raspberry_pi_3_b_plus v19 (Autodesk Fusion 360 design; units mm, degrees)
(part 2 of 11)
sketch "Sketch5" plane through (-0.5, 0, 0) normal (1, 0, 0) x axis (0, 0, -1)
  line L1 (-2.15, -3.125) -> (-2.15, -2.75)
  line L2 (-0.6, -3.425) -> (-1.85, -3.425)
  line L3 (-0.3, -1.71) -> (-0.3, -3.125)
  line L4 (0, -1.71) -> (-0.3, -1.71)
  line L5 (0, 1.71) -> (0, -1.71)
  line L6 (-0.3, 1.71) -> (0, 1.71)
  line L7 (-0.3, 3.125) -> (-0.3, 1.71)
  line L8 (-1.85, 3.425) -> (-0.6, 3.425)
  line L9 (-2.15, 2.75) -> (-2.15, 3.125)
  line L10 (-1.8, 2.4) -> (-2.15, 2.75)
  line L11 (-1.8, 1.9) -> (-1.8, 2.4)
  line L12 (-2.15, 1.55) -> (-1.8, 1.9)
  line L13 (-2.15, -1.55) -> (-2.15, 1.55)
  line L14 (-1.8, -1.9) -> (-2.15, -1.55)
  line L15 (-1.8, -2.4) -> (-1.8, -1.9)
  line L16 (-2.15, -2.75) -> (-1.8, -2.4)
  line L17 (-1.82, 1.74) -> (-1.82, -1.74)
  line L18 (-1.22, 1.74) -> (-1.82, 1.74)
  line L19 (-1.22, 1.5) -> (-1.22, 1.74)
  line L20 (-1.37, 1.5) -> (-1.22, 1.5)
  line L21 (-1.37, 1.1) -> (-1.37, 1.5)
  line L22 (-1.22, 1.1) -> (-1.37, 1.1)
  line L23 (-1.22, 0.85) -> (-1.22, 1.1)
  line L24 (-1.37, 0.85) -> (-1.22, 0.85)
  line L25 (-1.37, 0.45) -> (-1.37, 0.85)
  line L26 (-1.22, 0.45) -> (-1.37, 0.45)
  line L27 (-1.22, 0.2) -> (-1.22, 0.45)
  line L28 (-1.37, 0.2) -> (-1.22, 0.2)
  line L29 (-1.37, -0.2) -> (-1.37, 0.2)
  line L30 (-1.22, -0.2) -> (-1.37, -0.2)
  line L31 (-1.22, -0.45) -> (-1.22, -0.2)
  line L32 (-1.37, -0.45) -> (-1.22, -0.45)
  line L33 (-1.37, -0.85) -> (-1.37, -0.45)
  line L34 (-1.22, -0.85) -> (-1.37, -0.85)
  line L35 (-1.22, -1.1) -> (-1.22, -0.85)
  line L36 (-1.37, -1.1) -> (-1.22, -1.1)
  line L37 (-1.37, -1.5) -> (-1.37, -1.1)
  line L38 (-1.22, -1.5) -> (-1.37, -1.5)
  line L39 (-1.22, -1.74) -> (-1.22, -1.5)
  line L40 (-1.82, -1.74) -> (-1.22, -1.74)
  line L41 (-1.82, 0) -> (0, 0)
  arc A1 centre (-1.85, -3.125) radius 0.3 clockwise from (-1.85, -3.425) to (-2.15, -3.125)
  arc A2 centre (-0.6, -3.125) radius 0.3 clockwise from (-0.3, -3.125) to (-0.6, -3.425)
  arc A3 centre (-0.6, 3.125) radius 0.3 clockwise from (-0.6, 3.425) to (-0.3, 3.125)
  arc A4 centre (-1.85, 3.125) radius 0.3 clockwise from (-2.15, 3.125) to (-1.85, 3.425)
  point P1 (0, 0)
  point P50 (0, 0)
  point P51 (-1.82, 0)
  point P27 (-1.82, 1.74)
  point P28 (-1.22, 1.74)
  vertical L29
  vertical L17
  horizontal L18
  horizontal L20
  vertical L21
  horizontal L22
  vertical L23
  horizontal L24
  vertical L25
  horizontal L26
  vertical L27
  horizontal L28
  horizontal L30
  vertical L31
  horizontal L32
  horizontal L34
  vertical L35
  horizontal L36
  vertical L33
  vertical L37
  horizontal L38
  vertical L39
  horizontal L40
  vertical L19
  collinear L27 L31
  collinear L23 L31
  collinear L19 L31
  collinear L31 L35
  collinear L31 L39
  collinear L29 L33
  collinear L29 L37
  collinear L25 L29
  collinear L21 L29
  equal L21 L29
  equal L25 L29
  equal L29 L33
  equal L29 L37
  equal L31 L35
  equal L27 L31
  equal L23 L31
  equal L19 L39
  coincident P1 P50
  midpoint L17 P51
  horizontal L41
  dimension "d174" distance L13 L17 = 0.33
  dimension "d175" distance L18 L40 = 3.48
  dimension "d178" distance L30 L32 = 0.25
  dimension "d179" distance L28 L30 = 0.4
  dimension "d180" distance P27 P28 = 0.6
  dimension "d181" distance L19 L21 = 0.15
extrude "Extrude6" add sketch "Sketch5" profile of L17 L18 L19 L20 L21 L22 L23 L24 L25 L26 L27 L28 L29 L30 L31 L32 L33 L34 L35 L36 L37 L38 L39 L40 along normal blind 2.68
fillet "Fillet2" radius 0.2
fillet "Fillet3" radius 0.1
fillet "Fillet4" radius 0.05
sketch "Sketch1" plane through (0, 0, 1.82) normal (0, 0, 1) x axis (1, 0, 0)
  line L1 (-0.5, -1.54) -> (-0.5, 1.54)
  line L2 (1.4, 1.45) -> (1.06, 1.45)
  line L3 (1.03, 0.45) -> (1.43, 0.45)
  line L4 (1.03, 1.42) -> (1.03, 0.45)
  line L5 (1.98, 1.54) -> (1.98, -1.54)
  line L6 (1.03, 0.2) -> (1.03, -0.2)
  line L7 (1.43, -0.2) -> (1.43, 0.2)
  line L8 (1.03, -0.2) -> (1.43, -0.2)
  line L9 (1.43, 0.2) -> (1.03, 0.2)
  line L10 (1.43, 0.45) -> (1.43, 1.42)
  line L11 (-1.2, 2.7457) -> (-1.2, 3.4)
  line L12 (-0.9634, 1.4482) -> (-1.0866, 1.6618)
  line L13 (-0.8, 3.4) -> (-0.8, 1.6)
  line L14 (-0.65, 1.45) -> (-0.55, 1.45)
  line L15 (-0.5, 1.5) -> (-0.5, 1.54)
  line L16 (-0.5, 1.54) -> (1.98, 1.54)
  line L17 (-1.1146, 2.6396) -> (-1.1854, 2.7104)
  line L18 (-0.95, 0.3464) -> (-0.95, 1.3982)
  line L19 (-1.2, 3.4) -> (-0.8, 3.4)
  line L20 (-1.1, 1.7118) -> (-1.1, 2.6043)
  line L21 (1.98, 0) -> (-0.95, 0)
  line L22 (1.03, -0.2) -> (1.43, 0.2)
  line L23 (1.43, -0.2) -> (1.03, 0.2)
  line L24 (-0.5, -1.54) -> (1.98, -1.54)
  line L25 (-0.5, -1.5) -> (-0.5, -1.54)
  line L26 (-0.65, -1.45) -> (-0.55, -1.45)
  line L27 (-0.8, -3.4) -> (-0.8, -1.6)
  line L28 (-1.2, -3.4) -> (-0.8, -3.4)
  line L29 (-1.2, -2.7457) -> (-1.2, -3.4)
  line L30 (-1.1146, -2.6396) -> (-1.1854, -2.7104)
  line L31 (-1.1, -1.7118) -> (-1.1, -2.6043)
  line L32 (-0.9634, -1.4482) -> (-1.0866, -1.6618)
  line L33 (-0.95, -0.3464) -> (-0.95, -1.3982)
  line L34 (1.4, -1.45) -> (1.06, -1.45)
  line L35 (1.43, -0.45) -> (1.43, -1.42)
  line L36 (1.03, -0.45) -> (1.43, -0.45)
  line L37 (1.03, -1.42) -> (1.03, -0.45)
  line L38 (-0.95, 1.425) -> (-0.95, 1.3982)
  line L39 (-0.95, 1.425) -> (-0.9634, 1.4482)
  line L40 (-1.1, 2.625) -> (-1.1, 2.6043)
  line L41 (-1.1, 2.625) -> (-1.1146, 2.6396)
  line L42 (1.98, -1.54) -> (-0.5, -1.54)
  line L43 (1.98, 1.54) -> (1.98, -1.54)
  line L44 (-0.5, 1.54) -> (1.98, 1.54)
  arc A1 centre (-0.65, 1.6) radius 0.15 clockwise from (-0.65, 1.45) to (-0.8, 1.6)
  arc A2 centre (-0.9, 0.3464) radius 0.05 clockwise from (-0.9071, 0.2969) to (-0.95, 0.3464)
  arc A3 centre (-1.05, 1.3982) radius 0.1 clockwise from (-0.9634, 1.4482) to (-0.95, 1.3982)
  circle C1 centre (-0.5, 0.75) radius 0.3
  arc A4 centre (1.06, 1.42) radius 0.03 clockwise from (1.03, 1.42) to (1.06, 1.45)
  arc A5 centre (-0.55, 1.5) radius 0.05 clockwise from (-0.5, 1.5) to (-0.55, 1.45)
  arc A6 centre (-1, 1.7118) radius 0.1 clockwise from (-1.0866, 1.6618) to (-1.1, 1.7118)
  arc A7 centre (1.4, 1.42) radius 0.03 clockwise from (1.4, 1.45) to (1.43, 1.42)
  arc A8 centre (-0.95, 0) radius 0.3 clockwise from (-0.9071, 0.2969) to (-0.9071, -0.2969)
  arc A9 centre (-1.15, 2.7457) radius 0.05 clockwise from (-1.1854, 2.7104) to (-1.2, 2.7457)
  arc A10 centre (-1.15, 2.6043) radius 0.05 clockwise from (-1.1146, 2.6396) to (-1.1, 2.6043)
  arc A11 centre (-0.55, -1.5) radius 0.05 clockwise from (-0.55, -1.45) to (-0.5, -1.5)
  arc A12 centre (-0.65, -1.6) radius 0.15 clockwise from (-0.8, -1.6) to (-0.65, -1.45)
  arc A13 centre (-1.15, -2.7457) radius 0.05 clockwise from (-1.2, -2.7457) to (-1.1854, -2.7104)
  arc A14 centre (-1.15, -2.6043) radius 0.05 clockwise from (-1.1, -2.6043) to (-1.1146, -2.6396)
  arc A15 centre (-1, -1.7118) radius 0.1 clockwise from (-1.1, -1.7118) to (-1.0866, -1.6618)
  arc A16 centre (-1.05, -1.3982) radius 0.1 clockwise from (-0.95, -1.3982) to (-0.9634, -1.4482)
  arc A17 centre (-0.9, -0.3464) radius 0.05 clockwise from (-0.95, -0.3464) to (-0.9071, -0.2969)
  circle C2 centre (-0.5, -0.75) radius 0.3
  arc A18 centre (1.06, -1.42) radius 0.03 clockwise from (1.06, -1.45) to (1.03, -1.42)
  arc A19 centre (1.4, -1.42) radius 0.03 clockwise from (1.43, -1.42) to (1.4, -1.45)
  point P25 (-0.95, 0)
  point P47 (-0.95, 0)
  point P48 (1.98, 0)
  point P23 (-0.5, 0)
  point P32 (-0.95, 0.3464)
  point P49 (1.23, 0)
  point P50 (-1.1962, 2.7266)
  point P18 (-0.8, 3.4)
  point P59 (-0.8, -3.4)
  point P19 (-1.2, 3.4)
  point P60 (-1.2, -3.4)
  point P20 (-1.1146, 2.6396)
  point P64 (-1.1146, -2.6396)
  point P21 (-1.1, 1.7118)
  point P67 (-1.1, -1.7118)
  point P24 (-1.1854, 2.7104)
  point P63 (-1.1854, -2.7104)
  point P26 (-1.0866, 1.6618)
  point P69 (-1.0866, -1.6618)
  point P27 (-0.65, 1.45)
  point P56 (-0.65, -1.45)
  point P28 (-0.5, 1.5)
  point P53 (-0.5, -1.5)
  point P31 (-0.95, 1.3982)
  point P72 (-0.95, -1.3982)
  point P73 (-0.95, -0.3464)
  point P34 (-0.9071, 0.2969)
  point P75 (-0.9071, -0.2969)
  point P37 (-0.55, 1.45)
  point P55 (-0.55, -1.45)
  point P38 (-1.1, 2.6043)
  point P66 (-1.1, -2.6043)
  point P40 (-1.2, 2.7457)
  point P61 (-1.2, -2.7457)
  point P41 (-0.9634, 1.4482)
  point P70 (-0.9634, -1.4482)
  point P43 (1.98, 1.54)
  point P51 (1.98, -1.54)
  point P44 (-0.5, 1.54)
  point P52 (-0.5, -1.54)
  point P45 (-0.8, 1.6)
  point P58 (-0.8, -1.6)
  point P33 (-0.9071, -0.2969)
  point P4 (1.43, 1.42)
  point P82 (1.43, -1.42)
  point P5 (1.4, 1.45)
  point P80 (1.4, -1.45)
  point P12 (1.03, 0.45)
  point P84 (1.03, -0.45)
  point P14 (1.06, 1.45)
  point P78 (1.06, -1.45)
  point P15 (1.03, 1.42)
  point P79 (1.03, -1.42)
  point P17 (1.43, 0.45)
  point P83 (1.43, -0.45)
  point P42 (1.98, 1.54)
  point P16 (1.98, -1.54)
  point P10 (-0.5, 0.75)
  point P85 (-0.95, 1.425)
  point P86 (-1.1, 2.625)
  coincident P25 P47
  midpoint L5 P48
  horizontal L21
  coincident P23 L21
  vertical L5
  horizontal L16
  vertical L13
  horizontal L19
  vertical L11
  vertical L20
  vertical L18
  vertical L4
  vertical L10
  horizontal L2
  horizontal L3
  horizontal L9
  vertical L6
  vertical L7
  horizontal L8
  horizontal L14
  vertical L15
  tangent L11 A9
  tangent L17 A9
  tangent L17 A10
  tangent L20 A10
  tangent L20 A6
  tangent L12 A6
  tangent L12 A3
  tangent L18 A3
  tangent A1 L13
  tangent A1 L14
  tangent L14 A5
  tangent L15 A5
  tangent L18 A2
  tangent A2 A8
  vertical P25 P32
  tangent L10 A7
  tangent L2 A7
  tangent L2 A4
  tangent L4 A4
  collinear L7 L10
  collinear L4 L6
  midpoint L22 P49
  coincident L21 P49
  equal A5 A10
  equal A9 A10
  equal A2 A9
  equal A3 A6
  midpoint A9 P50
  equal A4 A7
  midpoint L1 P23
  symmetric P18 L21 P59
  symmetric P19 L21 P60
  symmetric P20 L21 P64
  symmetric P21 L21 P67
  symmetric P24 L21 P63
  symmetric P26 L21 P69
  symmetric P27 L21 P56
  symmetric P28 L21 P53
  symmetric P31 L21 P72
  symmetric P32 L21 P73
  symmetric P34 L21 P75
  symmetric P37 L21 P55
  symmetric P38 L21 P66
  symmetric P40 L21 P61
  symmetric P41 L21 P70
  symmetric P43 L21 P51
  symmetric P44 L21 P52
  symmetric P45 L21 P58
  symmetric A1 L21 A12
  symmetric A2 L21 A17
  symmetric A3 L21 A16
  symmetric A5 L21 A11
  symmetric A6 L21 A15
  symmetric A9 L21 A13
  symmetric A10 L21 A14
  coincident P33 P75
  symmetric P4 L21 P82
  symmetric P5 L21 P80
  symmetric P12 L21 P84
  symmetric P14 L21 P78
  symmetric P15 L21 P79
  symmetric P17 L21 P83
  symmetric C1 L21 C2
  symmetric A4 L21 A18
  symmetric A7 L21 A19
  tangent A3 L38
  tangent A3 L39
  tangent A10 L40
  parallel L20 L40
  tangent A10 L41
  parallel L17 L41
  coincident P42 P43
  coincident P16 P51
  coincident L1 P10
  dimension "d192" radius A8 = 0.3
  dimension "d193" diameter C1 = 0.6
  dimension "d195" distance P23 P25 = 0.45
  dimension "d196" distance L11 L13 = 0.4
  dimension "d197" distance L13 L20 = 0.3
  dimension "d200" distance P25 L19 = 3.4
  dimension "d201" distance P10 L21 = 0.75
  dimension "d203" distance L6 L7 = 0.4
  dimension "d204" distance L8 L9 = 0.4
  dimension "d206" distance L5 P49 = 0.75
  dimension "d208" distance L2 L3 = 1
  dimension "d209" distance L3 L9 = 0.25
  dimension "d210" radius A3 = 0.1
  dimension "d212" radius A1 = 0.15
  dimension "d213" radius A5 = 0.05
  dimension "d214" distance L14 L16 = 0.09
  dimension "d215" distance L13 L15 = 0.3
  dimension "d218" distance P23 L13 = 0.3
  dimension "d223" radius A7 = 0.03
  dimension "d225" angle L12 L18 = 150.018
  dimension "d227" distance L21 P85 = 1.425
  dimension "d228" angle L17 L20 = 135
  dimension "d229" distance P85 P86 = 1.2
face "Face1" sketch "Sketch1"
face "EdgeFlange2" FlangeHeight 0.16 FlangeAngle 90 BendRadius 0.05 TwoBendReliefSize 0.4
combine "Combine1"
sketch "Sketch1" plane through (0, 0, 1.37) normal (0, 0, -1) x axis (-1, 0, 0)
  line L1 (1.2, 0.175) -> (-1.3, 0.175)
  line L2 (1.2, -0.175) -> (1.2, 0.175)
  line L3 (-1.3, -0.175) -> (1.2, -0.175)
  line L4 (-1.3, 0.175) -> (-1.3, -0.175)
  line L5 (1.2, 0) -> (0, 0)
  point P1 (0, 0)
  point P6 (0, 0)
  point P7 (1.2, 0)
  horizontal L1
  vertical L2
  horizontal L3
  vertical L4
  coincident P1 P6
  midpoint L2 P7
  horizontal L5
  dimension "d239" distance L2 L4 = 2.5
  dimension "d240" distance L1 L3 = 0.35
  dimension "d241" distance P1 L2 = 1.2
face "Face1" sketch "Sketch1"
face "EdgeFlange2" FlangeHeight 0.3 FlangeAngle 90
face "EdgeFlange3" FlangeHeight 1.5 FlangeAngle 90
face "EdgeFlange4" FlangeHeight 0.8 FlangeAngle 90
step "Unfold1"
sketch "Sketch2" plane through (0, 0, 1.37) normal (0, 0, 1) x axis (1, 0, 0)
  line L1 (-2.5467, 0.175) -> (-2.5467, -0.175)
  line L2 (-3.1867, 0.175) -> (-2.5467, 0.175)
  line L3 (-3.1867, -0.175) -> (-3.1867, 0.175)
  line L4 (-2.5467, -0.175) -> (-3.1867, -0.175)
  line L5 (-4.3006, 0) -> (0, 0)
  line L6 (-0.9766, 0.125) -> (-3.1867, 0.125)
  line L7 (-1.04, 0.175) -> (1.14, 0.175)
  line L8 (-1.2034, 0.175) -> (-1.04, 0.175)
  line L9 (-2.3834, 0.175) -> (-1.2034, 0.175)
  line L10 (-2.3834, 0.175) -> (-2.5467, 0.175)
  line L11 (-2.3834, -0.175) -> (-2.5467, -0.175)
  line L12 (-1.2034, -0.175) -> (-2.3834, -0.175)
  line L13 (-1.04, -0.175) -> (-1.2034, -0.175)
  line L14 (1.14, -0.175) -> (-1.04, -0.175)
  line L15 (-0.9766, -0.125) -> (-3.1867, -0.125)
  arc A1 centre (-0.9766, 0.175) radius 0.05 clockwise from (-0.9333, 0.15) to (-0.9766, 0.125)
  arc A2 centre (-0.89, 0.125) radius 0.05 clockwise from (-0.9333, 0.15) to (-0.89, 0.175)
  arc A3 centre (-0.9766, -0.175) radius 0.05 clockwise from (-0.9766, -0.125) to (-0.9333, -0.15)
  arc A4 centre (-0.89, -0.125) radius 0.05 clockwise from (-0.89, -0.175) to (-0.9333, -0.15)
  point P1 (0, 0)
  point P6 (0, 0)
  point P8 (-3.1867, 0.125)
  point P12 (-0.89, 0.175)
  point P24 (-3.1867, -0.125)
  point P9 (-0.9766, 0.125)
  point P25 (-0.9766, -0.125)
  point P10 (-0.9333, 0.15)
  point P27 (-0.9333, -0.15)
  point P29 (-0.89, -0.175)
  point P15 (-1.04, 0.175)
  coincident P1 P6
  horizontal L5
  coincident L3 P8
  tangent L6 A1
  tangent A1 A2
  horizontal L6
  coincident P12 L7
  tangent A2 L7
  symmetric L5 P8 P24
  symmetric L5 P9 P25
  symmetric L5 P10 P27
  symmetric L5 A1 A3
  symmetric L5 P12 P29
  symmetric L5 A2 A4
  equal A1 A2
  dimension "d248" distance L6 L15 = 0.25
  dimension "d250" radius A1 = 0.05
  dimension "d251" distance P12 P15 = 0.15
extrude "Extrude1" cut sketch "Sketch2" profile of L2 L3 L4 L6 A1 A2 L7 L8 L9 L10 L11 L12 L13 L14 L15 A3 A4 no distance stored
step "Refold1"
rectangular_pattern "㐁" uSpaceDistance 0.65 vSpaceDistance 0
combine "Combine2"
sketch "Sketch8" plane through (2.03, 0, 0) normal (-1, 0, 0) x axis (0, 0, 1)
  line L1 (2.15, 1.975) -> (2.45, 1.975)
  line L2 (2.45, 2.775) -> (2.15, 2.775)
  line L3 (2.45, 1.975) -> (2.45, 2.775)
  line L4 (2.15, 1.975) -> (2.15, 2.775)
  line L5 (2.6, 2.2348) -> (2.6, 2.5152)
  line L6 (2.45, 2.375) -> (2.6, 2.375)
  line L7 (2.32, 2.3023) -> (2.32, 2.4477)
  arc A1 centre (2.35, 2.5152) radius 0.25 clockwise from (2.475, 2.7317) to (2.6, 2.5152)
  arc A2 centre (2.5, 2.775) radius 0.05 clockwise from (2.475, 2.7317) to (2.45, 2.775)
  arc A3 centre (2.35, 2.2348) radius 0.25 clockwise from (2.6, 2.2348) to (2.475, 2.0183)
  arc A4 centre (2.5, 1.975) radius 0.05 clockwise from (2.45, 1.975) to (2.475, 2.0183)
  arc A5 centre (2.5, 2.775) radius 0.35 clockwise from (2.2988, 2.4886) to (2.15, 2.775)
  arc A6 centre (2.5, 1.975) radius 0.35 clockwise from (2.15, 1.975) to (2.2988, 2.2614)
  arc A7 centre (2.27, 2.4477) radius 0.05 clockwise from (2.2988, 2.4886) to (2.32, 2.4477)
  arc A8 centre (2.27, 2.3023) radius 0.05 clockwise from (2.32, 2.3023) to (2.2988, 2.2614)
  point P11 (2.6, 2.375)
  point P12 (2.45, 2.375)
  point P6 (2.45, 2.775)
  point P15 (2.45, 2.775)
  point P13 (2.475, 2.7317)
  point P19 (2.475, 2.0183)
  point P21 (2.45, 1.975)
  point P23 (2.2988, 2.4886)
  point P25 (2.2988, 2.2614)
  point P4 (2.15, 2.775)
  point P24 (2.15, 2.775)
  vertical L5
  midpoint L5 P11
  midpoint L3 P12
  horizontal L6
  tangent L5 A1
  coincident P6 P15
  tangent A1 A2
  tangent L3 A2
  symmetric L6 P13 P19
  symmetric L6 A1 A3
  symmetric L6 P15 P21
  symmetric L6 A2 A4
  concentric A2 A5
  concentric A4 A6
  tangent A5 A7
  tangent A7 L7
  tangent L7 A8
  equal A7 A8
  tangent A6 A8
  symmetric L6 P23 P25
  coincident P4 P24
  dimension "d258" distance L3 L5 = 0.15
  dimension "d259" radius A1 = 0.25
  dimension "d260" radius A2 = 0.05
  dimension "d265" distance L5 L7 = 0.28 (= "muc_shell_thickness - 0.02 mm")
  dimension "d266" radius A7 = 0.05
loft "Loft2" sketch "Sketch8" End TakeOff Angle 0
mirror "Mirror2"
sketch "Sketch1" plane through (0, 0, 0) normal (0, 1, 0) x axis (1, 0, 0)
  line L1 (-6, -5.7) -> (6, -5.7)
  line L2 (-6, 5.7) -> (-6, -5.7)
  line L3 (6, 5.7) -> (-6, 5.7)
  line L4 (6, -5.7) -> (6, 5.7)
  line L5 (-6, 5.7) -> (6, -5.7)
  line L6 (6, 5.7) -> (-6, -5.7)
  point P6 (0, 0)
  point P1 (0, 0)
  point P4 (-6, 5.7)
  point P5 (6, 5.7)
  point P3 (-6, -5.7)
  perpendicular L1 L2
  parallel L1 L3
  parallel L2 L4
  horizontal L1
  coincident L5 P6
  coincident L6 P6
  coincident P1 P6
  dimension "d1_1" distance P4 P5 = 12 (= "sdc_width")
  dimension "d2_1" distance P3 P4 = 11.4 (= "sdc_length")
work_plane "WorkPlane1" sketch "Sketch1" AlongDistance 1.42 (= "sdc_height") named "d69_2"
sketch "Sketch2" plane through (0, 1.42, 0) normal (0, 1, 0) x axis (-1, 0, 0)
  line L1 (4.795, -2.48) -> (4.395, -2.48)
  line L2 (-1.805, -1.88) -> (-2.205, -1.88)
  line L3 (-5.24, -3.47) -> (-5.24, -4.67)
  line L4 (-2.405, -2.08) -> (-2.405, -2.48)
  line L5 (-3.19, -4.47) -> (-3.19, -3.47)
  line L6 (-1.605, -2.48) -> (-1.605, -2.08)
  line L7 (4.195, -2.28) -> (4.195, -1.88)
  line L8 (-3.79, -2.87) -> (-4.64, -2.87)
  line L9 (-2.205, -2.68) -> (-1.805, -2.68)
  line L10 (4.995, -1.88) -> (4.995, -2.28)
  line L11 (4.395, -1.68) -> (4.795, -1.68)
  line L12 (-1.105, -2.48) -> (-0.705, -2.48)
  line L13 (0.595, -2.28) -> (0.595, -1.63)
  line L14 (-0.505, -2.28) -> (-0.505, -1.88)
  line L15 (-5.2375, 2.05) -> (-5.0375, 2.05)
  line L16 (-2.705, -2.28) -> (-2.705, -1.88)
  line L17 (-4.79, -0.37) -> (-4.99, -0.37)
  line L18 (-0.205, -1.63) -> (-0.205, -2.28)
  line L19 (-5.29, -0.67) -> (-5.29, -0.97)
  line L20 (2.795, -2.28) -> (2.795, -1.63)
  line L21 (-5.4375, 2.85) -> (-5.4375, 2.25)
  line L22 (1.995, -1.63) -> (1.995, -2.28)
  line L23 (-0.705, -1.68) -> (-1.105, -1.68)
  line L24 (-3.505, -1.88) -> (-3.505, -2.28)
  line L25 (-4.49, -0.97) -> (-4.49, -0.67)
  line L26 (-2.905, -1.68) -> (-3.305, -1.68)
  line L27 (3.295, -2.48) -> (3.695, -2.48)
  line L28 (0.395, -1.43) -> (-0.005, -1.43)
  line L29 (1.695, -2.28) -> (1.695, -1.88)
  line L30 (1.095, -2.48) -> (1.495, -2.48)
  line L31 (-1.305, -1.88) -> (-1.305, -2.28)
  line L32 (0.895, -1.88) -> (0.895, -2.28)
  line L33 (-4.8375, 2.25) -> (-4.8375, 2.85)
  line L34 (1.495, -1.68) -> (1.095, -1.68)
  line L35 (-3.7875, 5.2) -> (-3.7875, 4.8)
  line L36 (4.766, -5.7) -> (4.766, -5.68)
  line L37 (3.895, -2.28) -> (3.895, -1.88)
  line L38 (-3.2875, 4.3) -> (-0.9075, 4.3)
  line L39 (2.195, -2.48) -> (2.595, -2.48)
  line L40 (-3.305, -2.48) -> (-2.905, -2.48)
  line L41 (5.366, -5.7) -> (5.366, -5.7001)
  line L42 (3.095, -1.88) -> (3.095, -2.28)
  line L43 (-0.7075, 4.3) -> (1.7925, 4.3)
  line L44 (6, -5.4) -> (5.666, -5.4)
  line L45 (5.75, 5.7) -> (5.75, -5.4)
  line L46 (-0.005, -2.48) -> (0.395, -2.48)
  line L47 (2.595, -1.43) -> (2.195, -1.43)
  line L48 (-4.84, -5.07) -> (-3.79, -5.07)
  line L49 (4.8725, 4.8) -> (4.8725, 5.4)
  line L50 (4.466, -5.38) -> (4.425, -5.38)
  line L51 (-5.675, -5.38) -> (-6, -5.38)
  line L52 (-4.99, -1.27) -> (-4.79, -1.27)
  line L53 (1.9925, 4.3) -> (4.3725, 4.3)
  line L54 (-5.675, -5.7) -> (-5.675, -5.38)
  line L55 (-5.0375, 3.05) -> (-5.2375, 3.05)
  line L56 (-2.875, -5.48) -> (-2.875, -5.7)
  line L57 (3.695, -1.68) -> (3.295, -1.68)
  line L58 (-5.75, -5.38) -> (-5.75, 5.7)
  line L59 (0.5425, 4.3) -> (0.5425, 5.7)
  line L60 (5.75, 5.7) -> (5.1725, 5.7)
  line L61 (-5.75, 5.7) -> (-4.2875, 5.7)
  line L62 (4.766, -5.7) -> (5.366, -5.7)
  line L63 (-5.675, -5.7) -> (-2.875, -5.7)
  line L64 (6, 5.7) -> (-6, 5.7)
  line L65 (-6, -5.7) -> (6, -5.7)
  line L66 (4.795, -2.28) -> (4.395, -1.88)
  line L67 (4.795, -1.88) -> (4.395, -2.28)
  line L68 (-5.0375, 2.85) -> (-5.2375, 2.25)
  line L69 (-5.2375, 2.85) -> (-5.0375, 2.25)
  line L70 (-4.64, -3.47) -> (-3.79, -4.47)
  line L71 (-5.29, -0.82) -> (-4.49, -0.82)
  line L72 (-4.89, -0.37) -> (-4.89, -1.27)
  line L73 (6, -5.7) -> (6, 5.7)
  line L74 (-6, 5.7) -> (-6, -5.7)
  line L75 (4.325, -5.7) -> (4.325, -5.48)
  line L76 (-2.675, -5.7) -> (-2.675, -5.48)
  line L77 (-1.675, -5.48) -> (-1.675, -5.7)
  line L78 (-1.475, -5.7) -> (-1.475, -5.48)
  line L79 (3.325, -5.48) -> (3.325, -5.7)
  line L80 (3.125, -5.7) -> (3.125, -5.48)
  line L81 (0.745, -5.7) -> (0.745, 5.7)
  arc A1 centre (-4.84, -4.67) radius 0.4 between (-5.24, -4.67) and (-4.84, -5.07)
  arc A2 centre (-2.205, -2.08) radius 0.2 between (-2.205, -1.88) and (-2.405, -2.08)
  arc A3 centre (4.795, -2.28) radius 0.2 clockwise from (4.995, -2.28) to (4.795, -2.48)
  arc A4 centre (-3.79, -3.47) radius 0.6 between (-3.19, -3.47) and (-3.79, -2.87)
  arc A5 centre (4.395, -2.28) radius 0.2 clockwise from (4.395, -2.48) to (4.195, -2.28)
  arc A6 centre (4.795, -1.88) radius 0.2 clockwise from (4.795, -1.68) to (4.995, -1.88)
  arc A7 centre (-3.79, -4.47) radius 0.6 between (-3.79, -5.07) and (-3.19, -4.47)
  arc A8 centre (-1.805, -2.08) radius 0.2 between (-1.605, -2.08) and (-1.805, -1.88)
  arc A9 centre (-2.205, -2.48) radius 0.2 between (-2.405, -2.48) and (-2.205, -2.68)
  arc A10 centre (4.395, -1.88) radius 0.2 clockwise from (4.195, -1.88) to (4.395, -1.68)
  arc A11 centre (-4.64, -3.47) radius 0.6 between (-4.64, -2.87) and (-5.24, -3.47)
  arc A12 centre (3.295, -2.28) radius 0.2 between (3.095, -2.28) and (3.295, -2.48)
  arc A13 centre (-4.99, -0.67) radius 0.3 between (-4.99, -0.37) and (-5.29, -0.67)
  arc A14 centre (-2.905, -1.88) radius 0.2 between (-2.705, -1.88) and (-2.905, -1.68)
  arc A15 centre (-1.805, -2.48) radius 0.2 between (-1.805, -2.68) and (-1.605, -2.48)
  arc A16 centre (3.695, -1.88) radius 0.2 between (3.895, -1.88) and (3.695, -1.68)
  arc A17 centre (-0.705, -1.88) radius 0.2 between (-0.505, -1.88) and (-0.705, -1.68)
  arc A18 centre (2.195, -1.63) radius 0.2 between (2.195, -1.43) and (1.995, -1.63)
  arc A19 centre (3.695, -2.28) radius 0.2 between (3.695, -2.48) and (3.895, -2.28)
  arc A20 centre (-2.905, -2.28) radius 0.2 between (-2.905, -2.48) and (-2.705, -2.28)
  arc A21 centre (-1.105, -2.28) radius 0.2 between (-1.305, -2.28) and (-1.105, -2.48)
  arc A22 centre (-4.79, -0.97) radius 0.3 between (-4.79, -1.27) and (-4.49, -0.97)
  arc A23 centre (-4.79, -0.67) radius 0.3 between (-4.49, -0.67) and (-4.79, -0.37)
  arc A24 centre (-1.105, -1.88) radius 0.2 between (-1.105, -1.68) and (-1.305, -1.88)
  arc A25 centre (1.095, -1.88) radius 0.2 between (1.095, -1.68) and (0.895, -1.88)
  arc A26 centre (-0.705, -2.28) radius 0.2 between (-0.705, -2.48) and (-0.505, -2.28)
  arc A27 centre (3.295, -1.88) radius 0.2 between (3.295, -1.68) and (3.095, -1.88)
  arc A28 centre (-5.2375, 2.85) radius 0.2 between (-5.2375, 3.05) and (-5.4375, 2.85)
  arc A29 centre (0.395, -1.63) radius 0.2 between (0.595, -1.63) and (0.395, -1.43)
  arc A30 centre (-3.305, -1.88) radius 0.2 between (-3.305, -1.68) and (-3.505, -1.88)
  arc A31 centre (-5.2375, 2.25) radius 0.2 between (-5.4375, 2.25) and (-5.2375, 2.05)
  arc A32 centre (2.595, -2.28) radius 0.2 between (2.595, -2.48) and (2.795, -2.28)
  arc A33 centre (1.495, -2.28) radius 0.2 between (1.495, -2.48) and (1.695, -2.28)
  arc A34 centre (2.195, -2.28) radius 0.2 between (1.995, -2.28) and (2.195, -2.48)
  arc A35 centre (-5.0375, 2.25) radius 0.2 between (-5.0375, 2.05) and (-4.8375, 2.25)
  arc A36 centre (1.495, -1.88) radius 0.2 between (1.695, -1.88) and (1.495, -1.68)
  arc A37 centre (-3.305, -2.28) radius 0.2 between (-3.505, -2.28) and (-3.305, -2.48)
  arc A38 centre (-0.005, -1.63) radius 0.2 between (-0.005, -1.43) and (-0.205, -1.63)
  arc A39 centre (5.1725, 5.4) radius 0.3 clockwise from (4.8725, 5.4) to (5.1725, 5.7)
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  point P173 (0.5425, 4.3)
  point P157 (1.8925, 4.3)
  point P164 (-0.8075, 4.3)
  point P169 (-5.75, 5.7)
  point P150 (-2.875, -5.7)
  point P122 (4.766, -5.7)
  point P133 (5.75, 5.7)
  point P35 (4.395, -1.88)
  point P178 (4.395, -1.88)
  point P11 (4.795, -2.28)
  point P179 (4.795, -2.28)
  point P17 (4.395, -2.28)
  point P180 (4.395, -2.28)
  point P21 (4.795, -1.88)
  point P181 (4.795, -1.88)
  point P182 (4.595, -2.08)
  point P103 (-5.2375, 2.25)
  point P183 (-5.2375, 2.25)
  point P142 (-5.0375, 2.85)
  point P184 (-5.0375, 2.85)
  point P113 (-5.0375, 2.25)
  point P185 (-5.0375, 2.25)
  point P97 (-5.2375, 2.85)
  point P186 (-5.2375, 2.85)
  point P187 (-5.1375, 2.55)
  point P24 (-3.79, -4.47)
  point P188 (-3.79, -4.47)
  point P36 (-4.64, -3.47)
  point P189 (-4.64, -3.47)
  point P190 (-4.215, -3.97)
  point P191 (-4.49, -0.82)
  point P192 (-5.29, -0.82)
  point P193 (-4.89, -1.27)
  point P194 (-4.89, -0.37)
  point P199 (-6, -5.38)
  point P166 (-5.75, -5.38)
  point P200 (6, -5.4)
  point P155 (5.75, -5.4)
  point P201 (4.325, -5.7)
  point P204 (-2.675, -5.7)
  point P205 (-1.675, -5.7)
  point P209 (-1.475, -5.7)
  point P210 (3.325, -5.7)
  point P214 (3.125, -5.7)
  point P208 (-1.575, -5.48)
  point P213 (3.225, -5.48)
  point P203 (-2.775, -5.48)
  point P215 (0.745, 5.7)
  point P216 (0.745, -5.7)
  point P172 (0.5425, 4.3)
  point P147 (5.366, -5.7)
  point P140 (4.325, -5.48)
  point P148 (5.666, -5.4)
  point P1 (0, 0)
  point P141 (4.425, -5.38)
  collinear L38 L43
  collinear L43 L53
  horizontal L43
  vertical L49
  vertical L35
  horizontal L47
  horizontal L11
  horizontal L57
  horizontal L34
  horizontal L28
  horizontal L23
  horizontal L2
  horizontal L26
  horizontal L8
  horizontal L55
  horizontal L17
  vertical L59
  midpoint L43 P173
  coincident L59 P173
  symmetric P157 P164 L59
  tangent A39 L49
  coincident L43 P157
  tangent L5 A7
  tangent A4 L5
  tangent A4 L8
  tangent L8 A11
  tangent L3 A11
  tangent A1 L3
  tangent A1 L48
  tangent A13 L17
  tangent A13 L19
  tangent A22 L52
  tangent A22 L25
  tangent A23 L25
  tangent L17 A23
  vertical L3
  horizontal L48
  vertical L5
  horizontal L52
  vertical L25
  vertical L19
  vertical L24
  horizontal L40
  vertical L16
  vertical L4
  horizontal L9
  vertical L6
  vertical L31
  horizontal L12
  vertical L14
  vertical L18
  horizontal L46
  vertical L13
  vertical L32
  horizontal L30
  vertical L29
  vertical L22
  horizontal L39
  vertical L20
  vertical L42
  horizontal L27
  vertical L37
  vertical L7
  horizontal L1
  vertical L10
  vertical L56
  vertical L54
  horizontal L51
  horizontal L44
  vertical L36
  horizontal L50
  collinear L1 L27
  collinear L1 L39
  collinear L1 L30
  collinear L1 L46
  collinear L1 L12
  collinear L1 L40
  tangent L24 A30
  tangent L24 A37
  tangent A37 L40
  tangent A20 L40
  tangent L16 A20
  tangent A14 L16
  tangent A14 L26
  tangent A2 L4
  tangent L4 A9
  tangent L9 A9
  tangent L9 A15
  tangent L6 A15
  tangent L6 A8
  tangent L2 A8
  tangent A2 L2
  tangent A30 L26
  tangent A24 L23
  tangent A24 L31
  tangent A21 L31
  tangent L12 A21
  tangent L12 A26
  tangent L14 A26
  tangent L14 A17
  tangent A17 L23
  tangent L28 A38
  tangent L18 A38
  tangent L13 A29
  tangent A29 L28
  tangent A7 L48
  tangent A25 L34
  tangent A25 L32
  tangent A33 L30
  tangent A33 L29
  tangent L29 A36
  tangent A36 L34
  tangent A18 L47
  tangent A18 L22
  tangent L22 A34
  tangent A34 L39
  tangent A32 L39
  tangent L20 A32
  tangent L1 A3
  tangent L1 A5
  tangent A5 L7
  tangent L7 A10
  tangent L11 A10
  tangent A6 L11
  tangent A6 L10
  tangent A3 L10
  tangent A27 L57
  tangent A27 L42
  tangent A12 L42
  tangent A12 L27
  tangent A19 L27
  tangent A19 L37
  tangent A16 L37
  tangent A16 L57
  equal A4 A7
  equal A7 A11
  equal A30 A37
  equal A20 A37
  equal A14 A20
  equal A2 A14
  equal A2 A9
  equal A9 A15
  equal A8 A15
  equal A8 A24
  equal A21 A24
  equal A21 A26
  equal A17 A26
  equal A17 A38
  equal A25 A29
  equal A33 A36
  equal A18 A36
  equal A18 A34
  equal A32 A34
  equal A12 A27
  equal A12 A19
  equal A16 A19
  equal A10 A16
  equal A5 A10
  equal A3 A5
  equal A3 A6
  vertical L21
  vertical L33
  horizontal L15
  tangent L15 A31
  tangent L15 A35
  tangent A35 L33
  tangent A28 L55
  tangent L21 A28
  tangent L21 A31
  equal A22 A23
  equal A28 A31
  equal A31 A35
  coincident P169 L64
  coincident P150 L65
  coincident P122 L65
  coincident P133 L64
  horizontal L61
  vertical L45
  horizontal L60
  tangent A39 L60
  coincident P35 P178
  coincident P11 P179
  coincident P17 P180
  coincident P21 P181
  midpoint L67 P182
  coincident P103 P183
  coincident P142 P184
  coincident P113 P185
  coincident P97 P186
  midpoint L68 P187
  coincident P24 P188
  coincident P36 P189
  midpoint L70 P190
  horizontal L63
  midpoint L25 P191
  midpoint L19 P192
  midpoint L52 P193
  midpoint L17 P194
  coincident L74 P199
  coincident P166 L51
  coincident L73 P200
  coincident P155 L44
  coincident L65 P201
  vertical L75
  horizontal L62
  coincident L65 P204
  perpendicular L65 L76
  coincident L65 P205
  perpendicular L65 L77
  coincident L65 P209
  perpendicular L65 L78
  coincident L65 P210
  perpendicular L65 L79
  coincident L65 P214
  perpendicular L65 L80
  horizontal P208 P213
  horizontal P203 P213
  coincident L64 P215
  coincident L65 P216
  vertical L81
  coincident P172 P173
  dimension "d7_2" radius A39 = 0.3
  dimension "d8_2" radius = 0.5
  dimension "d9_1" radius = 0.1
  dimension "d11_2" distance P157 P164 = 2.7
  dimension "d13_2" distance L35 L49 = 8.66
  dimension "d16_2" distance L36 P147 = 0.6
  dimension "d17_2" radius = 0.1
  dimension "d18_2" radius = 0.3
  dimension "d19_2" radius = 0.3
  dimension "d20_2" distance P140 L45 = 1.425
  dimension "d22_2" distance L8 L48 = 2.2
  dimension "d23_2" distance L3 L5 = 2.05
  dimension "d24_2" distance L26 L40 = 0.8
  dimension "d25_2" distance L16 L24 = 0.8
  dimension "d26_2" distance L4 L6 = 0.8 (= "d25_2")
  dimension "d27_2" distance L2 L9 = 0.8 (= "d24_2")
  dimension "d28_2" distance L12 L23 = 0.8 (= "d24_2")
  dimension "d29_2" distance L14 L31 = 0.8 (= "d25_2")
  dimension "d30_2" distance L13 L18 = 0.8 (= "d25_2")
  dimension "d31_2" distance L28 L46 = 1.05
  dimension "d32_2" distance L30 L34 = 0.8 (= "d24_2")
  dimension "d33_2" distance L29 L32 = 0.8 (= "d25_2")
  dimension "d34_1" distance L39 L47 = 1.05 (= "d31_2")
  dimension "d35_2" distance L20 L22 = 0.8 (= "d25_2")
  dimension "d36_2" distance L37 L42 = 0.8 (= "d25_2")
  dimension "d37_2" distance L7 L10 = 0.8 (= "d25_2")
  dimension "d38_1" distance L27 L57 = 0.8 (= "d24_2")
  dimension "d39_1" distance L1 L11 = 0.8 (= "d24_2")
  dimension "d41_1" distance L9 L12 = 0.2
  dimension "d42_1" distance L54 L58 = 0.075
  dimension "d44_2" distance L54 L56 = 2.8
  dimension "d45_2" radius A1 = 0.4
  dimension "d46_2" radius A11 = 0.6
  dimension "d49_2" distance P148 P155 = 0.084
  dimension "d51_2" distance L10 L37 = 1.1
  dimension "d52_2" distance L20 L37 = 1.1 (= "d51_2")
  dimension "d53_2" distance L20 L29 = 1.1 (= "d51_2")
  dimension "d54_2" distance L13 L29 = 1.1 (= "d51_2")
  dimension "d55_1" distance L13 L14 = 1.1 (= "d51_2")
  dimension "d56_1" distance L6 L14 = 1.1 (= "d51_2")
  dimension "d57_1" distance L6 L16 = 1.1 (= "d51_2")
  dimension "d58_1" radius A30 = 0.2
  dimension "d59_1" distance L17 L52 = 0.9
  dimension "d60_1" distance L19 L25 = 0.8
  dimension "d61_2" distance L21 L33 = 0.6
  dimension "d62_1" distance L15 L55 = 1
  dimension "d67_1" radius A13 = 0.3
  dimension "d68_1" radius A28 = 0.2
  dimension "d70_2" distance P1 L45 = 5.75
  dimension "d71_1" distance P1 L58 = 5.75
  dimension "d74_1" distance P1 L43 = 4.3
  dimension "d76_1" distance P1 P182 = 2.08
  dimension "d80" distance L61 P187 = 3.15
  dimension "d82_1" distance P1 P190 = 4.215
  dimension "d83_1" distance P1 P190 = 3.97
  dimension "d84_1" distance L51 L63 = 0.32
  dimension "d85" distance P1 L71 = 0.82
  dimension "d86" distance P1 L72 = 4.89
  dimension "d89_1" distance L44 L65 = 0.3
  dimension "d92_1" distance P141 L65 = 0.32
  dimension "d93_1" radius = 0.1
  dimension "d94_1" distance L65 P213 = 0.22
  dimension "d95_1" distance L75 L79 = 1
  dimension "d96_1" distance L76 L77 = 1
  dimension "d171_1" distance P1 L81 = 0.745
  dimension "d172_1" distance P182 L81 = 3.85 (= "( 7.7 / 2 ) * 1 mm")
  dimension "d174_1" distance L59 L81 = 0.2025 (= "( ( 7.7 / 2 - 3.105 ) / 2 ) * 1 mm - ( 0.34 / 2 ) * 1 mm")
  dimension "d176" distance P187 L74 = 0.8625
face "Face2" sketch "Sketch2"
face "EdgeFlange3" FlangeHeight 1.42 (= "sdc_height") named "d90_1" FlangeAngle 90 named "d91_1"
step "Unfold1"
sketch "Sketch1" plane through (0, 1.42, 0) normal (0, 1, 0) x axis (-1, 0, 0)
  line L1 (4.365, -5.4) -> (3.285, -5.4)
  line L2 (4.466, -5.38) -> (4.425, -5.38)
  line L3 (4.766, -5.7) -> (4.766, -5.68)
  line L4 (5.366, -5.7) -> (4.766, -5.7)
  line L5 (5.7, -5.4) -> (5.666, -5.4)
  line L6 (5.7, 5.7) -> (5.7, -5.4)
  line L7 (5.1725, 5.7) -> (5.7, 5.7)
  line L8 (4.8725, 4.8) -> (4.8725, 5.4)
  line L9 (1.9925, 4.3) -> (4.3725, 4.3)
  line L10 (-0.7075, 4.3) -> (1.7925, 4.3)
  line L11 (-3.2875, 4.3) -> (-0.9075, 4.3)
  line L12 (-3.7875, 5.2) -> (-3.7875, 4.8)
  line L13 (-5.7, 5.7) -> (-4.2875, 5.7)
  line L14 (-5.7, -5.38) -> (-5.7, 5.7)
  line L15 (-5.675, -5.38) -> (-5.7, -5.38)
  line L16 (-5.675, -5.7) -> (-5.675, -5.38)
  line L17 (-2.875, -5.7) -> (-5.675, -5.7)
  line L18 (-2.875, -5.48) -> (-2.875, -5.7)
  line L19 (-1.635, -5.4) -> (-2.715, -5.4)
  line L20 (3.165, -5.4) -> (-1.515, -5.4)
  line L21 (-1.305, -1.88) -> (-1.305, -2.28)
  line L22 (-0.705, -1.68) -> (-1.105, -1.68)
  line L23 (-0.505, -2.28) -> (-0.505, -1.88)
  line L24 (-1.105, -2.48) -> (-0.705, -2.48)
  line L25 (-3.305, -2.48) -> (-2.905, -2.48)
  line L26 (-3.505, -1.88) -> (-3.505, -2.28)
  line L27 (-2.905, -1.68) -> (-3.305, -1.68)
  line L28 (-2.705, -2.28) -> (-2.705, -1.88)
  line L29 (-1.605, -2.48) -> (-1.605, -2.08)
  line L30 (-2.205, -2.68) -> (-1.805, -2.68)
  line L31 (-2.405, -2.08) -> (-2.405, -2.48)
  line L32 (-1.805, -1.88) -> (-2.205, -1.88)
  line L33 (4.795, -1.68) -> (4.395, -1.68)
  line L34 (4.995, -2.28) -> (4.995, -1.88)
  line L35 (4.395, -2.48) -> (4.795, -2.48)
  line L36 (4.195, -1.88) -> (4.195, -2.28)
  line L37 (-4.84, -5.07) -> (-3.79, -5.07)
  line L38 (-5.24, -3.47) -> (-5.24, -4.67)
  line L39 (-3.79, -2.87) -> (-4.64, -2.87)
  line L40 (-3.19, -4.47) -> (-3.19, -3.47)
  line L41 (2.595, -1.43) -> (2.195, -1.43)
  line L42 (2.795, -2.28) -> (2.795, -1.63)
  line L43 (2.195, -2.48) -> (2.595, -2.48)
  line L44 (1.995, -1.63) -> (1.995, -2.28)
  line L45 (-5.0375, 3.05) -> (-5.2375, 3.05)
  line L46 (-4.8375, 2.25) -> (-4.8375, 2.85)
  line L47 (-5.2375, 2.05) -> (-5.0375, 2.05)
  line L48 (-5.4375, 2.85) -> (-5.4375, 2.25)
  line L49 (-0.005, -2.48) -> (0.395, -2.48)
  line L50 (-0.205, -1.63) -> (-0.205, -2.28)
  line L51 (0.395, -1.43) -> (-0.005, -1.43)
  line L52 (0.595, -2.28) -> (0.595, -1.63)
  line L53 (3.695, -1.68) -> (3.295, -1.68)
  line L54 (3.895, -2.28) -> (3.895, -1.88)
  line L55 (3.295, -2.48) -> (3.695, -2.48)
  line L56 (3.095, -1.88) -> (3.095, -2.28)
  line L57 (1.095, -2.48) -> (1.495, -2.48)
  line L58 (0.895, -1.88) -> (0.895, -2.28)
  line L59 (1.495, -1.68) -> (1.095, -1.68)
  line L60 (1.695, -2.28) -> (1.695, -1.88)
  line L61 (-4.99, -1.27) -> (-4.79, -1.27)
  line L62 (-5.29, -0.67) -> (-5.29, -0.97)
  line L63 (-4.79, -0.37) -> (-4.99, -0.37)
  line L64 (-4.49, -0.97) -> (-4.49, -0.67)
  line L65 (-6.0393, 5.7) -> (-6.0393, -5.38)
  line L66 (-7.1593, 5.7) -> (-6.0393, 5.7)
  line L67 (-7.1593, -5.38) -> (-7.1593, 5.7)
  line L68 (-6.0393, -5.38) -> (-7.1593, -5.38)
  line L69 (6.0393, -5.4) -> (6.0393, 5.7)
  line L70 (7.1593, -5.4) -> (6.0393, -5.4)
  line L71 (7.1593, 5.7) -> (7.1593, -5.4)
  line L72 (6.0393, 5.7) -> (7.1593, 5.7)
  line L73 (-5.4393, 3.8) -> (-6.0393, 3.8)
  line L74 (-5.4393, 4.4) -> (-5.4393, 3.8)
  line L75 (-6.0393, 4.4) -> (-5.4393, 4.4)
  line L76 (-6.0393, 3.8) -> (-6.0393, 4.4)
  line L77 (5.7, 3.35) -> (6.0393, 3.35)
  line L78 (5.7, 3.95) -> (5.7, 3.35)
  line L79 (6.0393, 3.95) -> (5.7, 3.95)
  line L80 (6.0393, 3.35) -> (6.0393, 3.95)
  line L81 (-6.4093, 4.85) -> (-7.1593, 4.85)
  line L82 (-6.7093, 3.55) -> (-6.8593, 3.55)
  line L83 (-6.4593, 1.65) -> (-6.4593, 3.3)
  line L84 (-6.9593, 1.55) -> (-6.5593, 1.55)
  line L85 (-6.5093, -0.9) -> (-6.8593, -0.9)
  line L86 (-7.0093, -1.65) -> (-6.5093, -1.65)
  line L87 (-6.7593, 3.8) -> (-6.4393, 3.8)
  line L88 (-6.8593, 4.3) -> (-6.8593, 3.9)
  line L89 (-6.4393, 4.4) -> (-6.7593, 4.4)
  line L90 (-6.3393, 3.9) -> (-6.3393, 4.3)
  line L91 (-6.8093, 4.65) -> (-6.4093, 4.65)
  line L92 (-7.1593, 4.1) -> (-5.4393, 4.1)
  line L93 (-7.1093, 3.8) -> (-7.1093, 4.35)
  line L94 (-6.6593, 0.95) -> (-6.9593, 0.95)
  line L95 (-6.9593, 0.85) -> (-6.6593, 0.85)
  line L96 (-6.9593, 0.95) -> (-6.9593, 1.55)
  line L97 (-6.9593, -0.8) -> (-6.9593, 0.85)
  line L98 (-6.8593, 3.55) -> (-7.1093, 3.8)
  line L99 (-6.4093, -1.55) -> (-6.4093, -1)
  line L100 (-7.1093, -3.7) -> (-7.1093, -1.75)
  line L101 (-6.6093, -5.28) -> (-6.6093, -4.2)
  line L102 (-6.7593, -3.65) -> (-6.4393, -3.65)
  line L103 (-6.8593, -2.5) -> (-6.8593, -3.55)
  line L104 (-6.4393, -2.4) -> (-6.7593, -2.4)
  line L105 (-6.3393, -3.55) -> (-6.3393, -2.5)
  line L106 (6.8593, 4.7) -> (7.1593, 4.7)
  line L107 (7.1593, 4.5) -> (6.8593, 4.5)
  line L108 (2.325, -6.2093) -> (2.325, -6.7593)
  line L109 (3.025, -6.1093) -> (2.425, -6.1093)
  line L110 (0.825, -5.9501) -> (0.825, -6.8593)
  line L111 (1.275, -6.1593) -> (0.375, -6.1593)
  line L112 (1.325, -6.5093) -> (1.325, -6.2093)
  line L113 (0.375, -6.5593) -> (1.275, -6.5593)
  line L114 (0.325, -6.2093) -> (0.325, -6.5093)
  line L115 (-0.675, -6.2093) -> (-0.675, -6.7593)
  line L116 (-1.375, -6.1093) -> (-0.775, -6.1093)
  line L117 (3.325, -5.7393) -> (4.325, -5.7393)
  line L118 (3.325, -6.8593) -> (3.325, -5.7393)
  line L119 (4.325, -6.8593) -> (3.325, -6.8593)
  line L120 (4.325, -5.7393) -> (4.325, -6.8593)
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  point P186 (-6.0393, 3.8)
  point P192 (5.7, 3.95)
  point P190 (6.0393, 3.35)
  point P194 (-7.1593, 4.85)
  point P204 (-5.4393, 4.1)
  point P205 (-7.1593, 4.1)
  point P206 (-6.3393, 4.1)
  point P248 (-6.5093, -5.38)
  point P243 (-6.9093, -3.9)
  point P246 (-6.9093, -4.2)
  point P262 (7.1593, 4.7)
  point P266 (7.1593, 4.5)
  point P276 (0.825, -6.1593)
  point P267 (2.325, -6.7593)
  point P293 (-0.675, -6.7593)
  point P268 (2.325, -6.2093)
  point P294 (-0.675, -6.2093)
  point P269 (2.425, -6.1093)
  point P296 (-0.775, -6.1093)
  point P271 (3.025, -6.1093)
  point P297 (-1.375, -6.1093)
  point P272 (3.125, -6.0093)
  point P299 (-1.475, -6.0093)
  point P289 (2.225, -6.8593)
  point P292 (-0.575, -6.8593)
  point P197 (-6.4093, 4.75)
  point P221 (-7.1093, 3.8)
  point P222 (-6.8593, 3.55)
  point P230 (-6.6593, 0.9)
  point P202 (-7.0093, -1.65)
  point P265 (6.8593, 4.6)
  point P182 (6.0393, 5.7)
  horizontal L73
  vertical L74
  horizontal L75
  vertical L76
  coincident L65 P186
  horizontal L77
  vertical L78
  horizontal L79
  vertical L80
  coincident L6 P192
  coincident L69 P190
  coincident L67 P194
  perpendicular L67 L81
  vertical L83
  horizontal L84
  vertical L96
  horizontal L86
  horizontal L87
  vertical L88
  horizontal L89
  vertical L90
  horizontal L91
  midpoint L74 P204
  coincident L67 P205
  horizontal L92
  coincident L92 P206
  collinear L73 L87
  coincident L90 P206
  collinear L75 L89
  horizontal L82
  vertical L93
  horizontal L85
  vertical L97
  horizontal L94
  horizontal L95
  collinear L96 L97
  vertical L99
  coincident L68 P248
  vertical L101
  vertical L100
  collinear L93 L100
  vertical P243 P246
  horizontal L102
  vertical L103
  horizontal L104
  vertical L105
  collinear L88 L103
  collinear L90 L105
  coincident L71 P262
  coincident L71 P266
  horizontal L107
  horizontal L106
  horizontal L109
  vertical L108
  vertical L110
  perpendicular L111 L112
  parallel L111 L113
  parallel L112 L114
  horizontal L111
  coincident L110 P276
  coincident L111 P276
  midpoint L111 P276
  symmetric P267 L110 P293
  symmetric P268 L110 P294
  symmetric P269 L110 P296
  symmetric P271 L110 P297
  symmetric P272 L110 P299
  symmetric L110 P289 P292
  dimension "d97" distance L66 L81 = 0.85
  dimension "d98_1" radius = 0.1
  dimension "d99_1" distance L67 P197 = 0.75
  dimension "d102_1" distance L66 L92 = 1.6
  dimension "d103_1" distance L65 L74 = 0.6
  dimension "d104_1" distance L73 L75 = 0.6
  dimension "d106_1" distance L76 L90 = 0.3
  dimension "d107_1" distance L67 L88 = 0.3
  dimension "d108_1" radius = 0.1
  dimension "d109_1" distance L88 L93 = 0.25
  dimension "d110_1" distance L82 L87 = 0.25
  dimension "d111_1" radius = 0.3
  dimension "d112_1" radius = 0.1
  dimension "d113_1" radius = 0.25
  dimension "d114_1" distance L67 L83 = 0.7
  dimension "d116_1" distance L82 L84 = 2
  dimension "d118_1" distance L83 L96 = 0.5
  dimension "d123" distance L84 L94 = 0.6
  dimension "d124_1" distance L85 L95 = 1.75
  dimension "d125_1" distance P221 P222 = 0.25
  dimension "d126_1" distance P221 P222 = 0.25
  dimension "d127_1" radius = 0.05
  dimension "d128_1" radius = 0.1
  dimension "d129_1" radius = 0.1
  dimension "d130_1" distance L67 L99 = 0.75
  dimension "d131_1" distance L85 L86 = 0.75
  dimension "d132_1" distance L97 P230 = 0.3
  dimension "d133_1" radius = 0.1
  dimension "d134_1" radius = 0.2
  dimension "d135_1" radius = 0.3
  dimension "d136_1" distance P202 P243 = 2.25
  dimension "d137_1" radius = 0.1
  dimension "d138_1" radius = 0.1
  dimension "d139_1" distance L86 L104 = 0.75
  dimension "d140_1" distance L102 L104 = 1.25
  dimension "d145_1" radius = 0.1
  dimension "d146" distance L72 L106 = 1
  dimension "d147" distance L71 P265 = 0.3
  dimension "d148" distance P182 L79 = 1.75
  dimension "d149" distance L77 L79 = 0.6
  dimension "d290" distance L111 L113 = 0.4
  dimension "d292" distance L112 L114 = 1
  dimension "d293" radius = 0.05
  dimension "d295" radius = 0.1
  dimension "d296" distance L108 L115 = 3
extrude "Extrude1" cut sketch "Sketch1" no distance stored
step "Refold1"
face "EdgeFlange4" FlangeHeight 0.4 FlangeAngle 90 named "d143_1" BendRadius 0.05 named "d144_1"
face "EdgeFlange5" FlangeHeight 0.75 named "d151_1" FlangeAngle 90 named "d152_1"
face "EdgeFlange6" FlangeHeight 1 named "d153_1" FlangeAngle 90 named "d154_1"
step "Unfold2"
sketch "Sketch2" plane through (0, 1.42, 0) normal (0, 1, 0) x axis (-1, 0, 0)
  line L1 (7.1986, 4.7) -> (7.1986, 5.7)
  line L2 (7.6486, 4.7) -> (7.1986, 4.7)
  line L3 (7.6486, 5.7) -> (7.6486, 4.7)
  line L4 (7.1986, 5.7) -> (7.6486, 5.7)
  line L5 (7.1986, 5.2) -> (7.6486, 5.2)
  line L6 (3.825, -6.8986) -> (3.825, -7.3486)
  line L7 (-2.175, -6.8986) -> (-2.175, -7.3486)
  line L8 (-2.675, -7.3486) -> (-1.675, -7.3486)
  line L9 (-1.675, -6.8986) -> (-2.675, -6.8986)
  line L10 (-1.675, -6.8986) -> (-2.675, -6.8986)
  line L11 (3.325, -7.3486) -> (4.325, -7.3486)
  line L12 (4.325, -6.8986) -> (3.325, -6.8986)
  line L13 (4.325, -6.8986) -> (3.325, -6.8986)
  arc A1 centre (7.5486, 5.45) radius 0.1 clockwise from (7.6486, 5.45) to (7.5486, 5.35)
  arc A2 centre (7.5486, 5.2) radius 0.15 clockwise from (7.5486, 5.05) to (7.5486, 5.35)
  arc A3 centre (7.5486, 4.95) radius 0.1 clockwise from (7.5486, 5.05) to (7.6486, 4.95)
  arc A4 centre (4.075, -7.2486) radius 0.1 clockwise from (4.075, -7.3486) to (3.975, -7.2486)
  arc A5 centre (3.575, -7.2486) radius 0.1 clockwise from (3.675, -7.2486) to (3.575, -7.3486)
  arc A6 centre (3.825, -7.2486) radius 0.15 clockwise from (3.675, -7.2486) to (3.975, -7.2486)
  arc A7 centre (-1.925, -7.2486) radius 0.1 clockwise from (-1.925, -7.3486) to (-2.025, -7.2486)
  arc A8 centre (-2.425, -7.2486) radius 0.1 clockwise from (-2.325, -7.2486) to (-2.425, -7.3486)
  arc A9 centre (-2.175, -7.2486) radius 0.15 clockwise from (-2.325, -7.2486) to (-2.025, -7.2486)
  point P6 (7.6486, 5.2)
  point P7 (7.1986, 5.2)
  point P8 (7.6486, 5.45)
  point P13 (7.6486, 4.95)
  point P9 (7.5486, 5.35)
  point P11 (7.5486, 5.05)
  point P12 (7.5486, 5.2)
  point P14 (7.5486, 4.95)
  point P20 (3.975, -7.2486)
  point P23 (3.675, -7.2486)
  point P24 (3.575, -7.2486)
  point P25 (3.825, -7.2486)
  point P27 (-2.025, -7.2486)
  point P29 (-2.325, -7.2486)
  point P31 (-2.425, -7.2486)
  point P32 (-2.175, -7.2486)
  midpoint L3 P6
  midpoint L1 P7
  tangent L3 A1
  coincident L3 P8
  tangent L3 A3
  coincident L3 P13
  tangent A1 A2
  tangent A2 A3
  symmetric L5 P9 P11
  vertical P12 P14
  tangent A5 A6
  tangent A4 A6
  symmetric L6 P20 P23
  horizontal P24 P25
  tangent A8 A9
  tangent A7 A9
  symmetric L7 P27 P29
  horizontal P31 P32
  equal A4 A5
  equal A7 A8
  dimension "d155" radius A2 = 0.15
  dimension "d156_1" radius A1 = 0.1
  dimension "d157_1" radius A6 = 0.15 (= "d155")
  dimension "d158_1" radius A4 = 0.1 (= "d156_1")
  dimension "d159_1" radius A9 = 0.15 (= "d155")
  dimension "d160_1" radius A7 = 0.1 (= "d156_1")
extrude "Extrude2" cut sketch "Sketch2" profile of L3 A1 A2 A3 A4 A5 A6 A7 A8 A9 no distance stored
step "Refold2"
